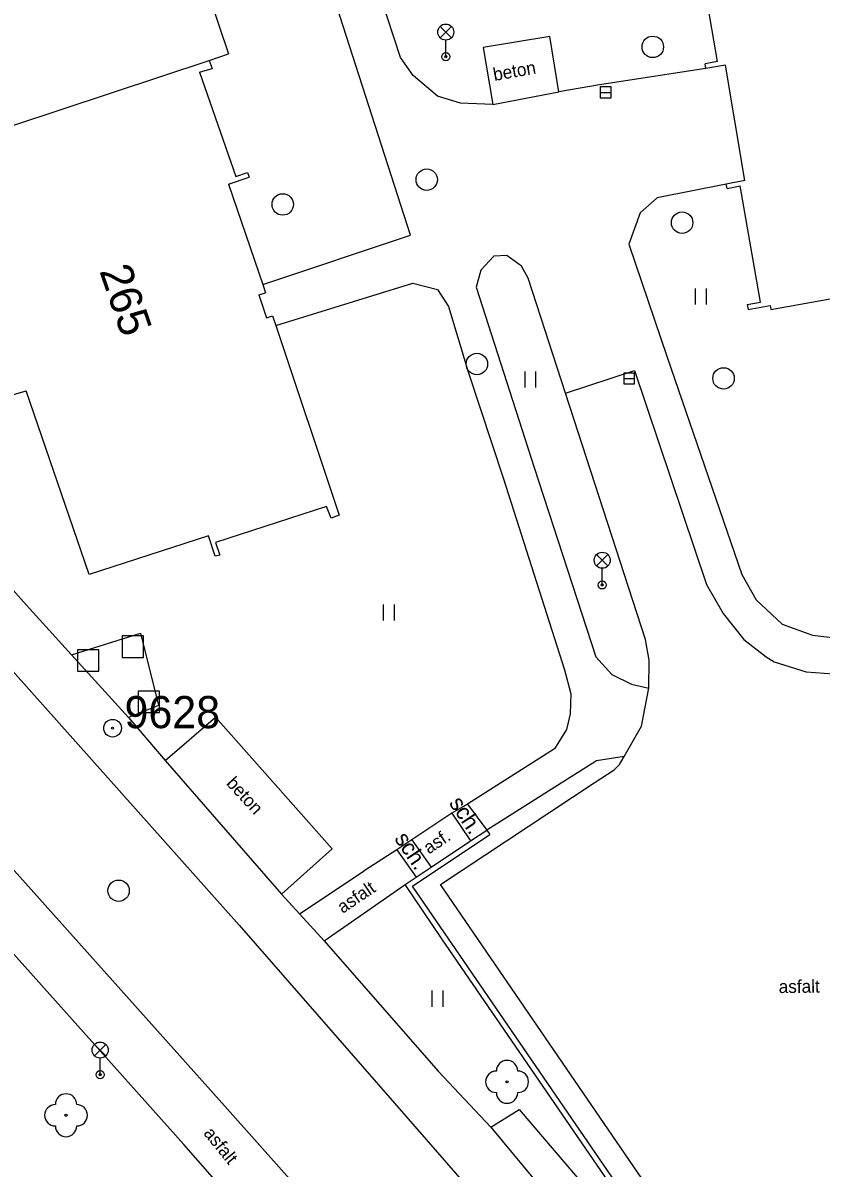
# Model space of a CAD drawing. Extents: x -492431 to -49218, y -1127123 to -112687.
# Drawn here: x -492324.3 to -492287, y -1126996.4 to -1126943 of the extents above; entities that cross this region are included whole.
import ezdxf

# ---------------------------------------------------------------- set-up
doc = ezdxf.new("R2010")
doc.units = 0
for name, color, linetype in [('Vrstva 10', 7, 'Continuous'), ('Vrstva 11', 7, 'Continuous'), ('Vrstva 22', 7, 'Continuous'), ('Vrstva 26', 7, 'Continuous'), ('Vrstva 27', 7, 'Continuous'), ('Vrstva 33', 7, 'Continuous'), ('Vrstva 36', 7, 'Continuous'), ('Vrstva 40', 7, 'Continuous'), ('Vrstva 42', 7, 'Continuous'), ('Vrstva 43', 7, 'Continuous'), ('Vrstva 5', 7, 'Continuous'), ('Vrstva 63', 7, 'Continuous')]:
    doc.layers.add(name, color=color, linetype=linetype)

msp = doc.modelspace()

# ---------------------------------------------------------------- linework, layer by layer
at = {"layer": 'Vrstva 10'}
for p, q in [((-492306.65, -1126944.57), (-492312.04, -1126928.07)), ((-492306.05, -1126945.42), (-492306.65, -1126944.57)), ((-492304.92, -1126946.38), (-492306.05, -1126945.42)), ((-492303.85, -1126946.71), (-492304.92, -1126946.38)), ((-492302.34, -1126946.76), (-492303.85, -1126946.71)), ((-492298.94, -1126960.23), (-492295.73, -1126959.17)), ((-492295.73, -1126959.17), (-492292.37, -1126969.15)), ((-492295.21, -1126971.71), (-492298.94, -1126960.23)), ((-492324.24, -1126969.96), (-492326.41, -1126967.51)), ((-492292.37, -1126969.15), (-492291.59, -1126970.51)), ((-492291.59, -1126970.51), (-492290.62, -1126971.71)), ((-492295.04, -1126972.68), (-492295.21, -1126971.71)), ((-492290.62, -1126971.71), (-492289.58, -1126972.52)), ((-492295.05, -1126973.99), (-492295.04, -1126972.68)), ((-492289.58, -1126972.52), (-492289.2, -1126972.75)), ((-492289.2, -1126972.75), (-492287.72, -1126973.22)), ((-492287.72, -1126973.22), (-492286.45, -1126973.32)), ((-492295.39, -1126975.75), (-492295.05, -1126973.99)), ((-492296.21, -1126977.17), (-492295.39, -1126975.75)), ((-492306.08, -1126983.22), (-492302.47, -1126980.81)), ((-492304.71, -1126985.68), (-492306.43, -1126983.14)), ((-492294.56, -1127000), (-492306.08, -1126983.22)), ((-492294.87, -1127000), (-492304.71, -1126985.68))]:
    msp.add_line(p, q, dxfattribs=at)
for points in [[(-492313.07, -1126955.16), (-492306.17, -1126952.86), (-492312.31, -1126933.84), (-492313.96, -1126934.43)], [(-492299.25, -1126946.17), (-492299.68, -1126943.6), (-492302.79, -1126944.11), (-492302.34, -1126946.76)], [(-492292.39, -1126945.09), (-492297.35, -1126945.85), (-492299.25, -1126946.17)], [(-492291.44, -1126950.48), (-492294.66, -1126951.12), (-492295.46, -1126951.82), (-492295.99, -1126953.28), (-492294.2, -1126958.55), (-492290.72, -1126968.68), (-492290.05, -1126969.86), (-492288.83, -1126971), (-492287.42, -1126971.52), (-492286.24, -1126971.66), (-492285.15, -1126971.46)], [(-492298.94, -1126960.23), (-492300.69, -1126954.87), (-492301, -1126954.31), (-492301.68, -1126953.81), (-492302.29, -1126953.84), (-492302.89, -1126954.49), (-492303.12, -1126955.29), (-492300.41, -1126963.69), (-492297.53, -1126972.53), (-492296.78, -1126973.35), (-492295.87, -1126973.8), (-492295.05, -1126973.99)], [(-492312.46, -1126957.08), (-492306.07, -1126955.1), (-492304.92, -1126955.4), (-492304.41, -1126956.18), (-492303.49, -1126959.24), (-492301.83, -1126964.22), (-492298.99, -1126973.13), (-492298.7, -1126974.25), (-492298.72, -1126975.18), (-492298.9, -1126975.91), (-492299.45, -1126976.82), (-492303.51, -1126979.39)], [(-492324.24, -1126969.96), (-492322, -1126972.43), (-492319.34, -1126975.35), (-492317.62, -1126977.35)], [(-492335.11, -1126970.78), (-492326.65, -1126980.29), (-492314.72, -1126993.62)], [(-492326.66, -1126971.05), (-492314.18, -1126985.03)], [(-492322, -1126972.43), (-492318.78, -1126971.42), (-492317.93, -1126974.79), (-492319.34, -1126975.35)], [(-492317.62, -1126977.35), (-492315.28, -1126975.33), (-492309.84, -1126981.47), (-492312.2, -1126983.59)], [(-492293.22, -1127000), (-492304.77, -1126983.14), (-492297.61, -1126978.4), (-492296.68, -1126977.79), (-492296.43, -1126977.55), (-492296.21, -1126977.17)], [(-492303.51, -1126979.39), (-492304.25, -1126979.82)], [(-492304.25, -1126979.82), (-492306.11, -1126981.06)], [(-492303.37, -1126981.11), (-492302.62, -1126980.61)], [(-492302.62, -1126980.61), (-492302.47, -1126980.81)], [(-492306.81, -1126981.53), (-492308.34, -1126982.51)], [(-492306.11, -1126981.06), (-492306.81, -1126981.53)], [(-492305.21, -1126982.33), (-492303.37, -1126981.11)], [(-492311.36, -1126984.5), (-492308.34, -1126982.51)], [(-492305.92, -1126982.8), (-492305.21, -1126982.33)], [(-492306.43, -1126983.14), (-492305.92, -1126982.8)], [(-492312.2, -1126983.59), (-492311.36, -1126984.5)], [(-492308.17, -1126984.35), (-492306.43, -1126983.14)], [(-492336.73, -1126985.35), (-492328.28, -1126983.94), (-492326.75, -1126984.43), (-492325.62, -1126985.37), (-492316.76, -1126995.26)], [(-492310.2, -1126985.76), (-492308.17, -1126984.35)], [(-492314.18, -1126985.03), (-492306.93, -1126993.34), (-492301.65, -1126999.39), (-492301.14, -1127000)], [(-492310.2, -1126985.76), (-492304.88, -1126991.85), (-492302.43, -1126994.46)], [(-492309.11, -1127000), (-492310.82, -1126998), (-492314.72, -1126993.62)], [(-492302.43, -1126994.46), (-492301.1, -1126993.63), (-492295.66, -1127000)], [(-492302.43, -1126994.46), (-492297.83, -1127000)], [(-492312.58, -1127000), (-492314.64, -1126997.68), (-492316.76, -1126995.26)]]:
    msp.add_lwpolyline(points, dxfattribs=at)
at = {"layer": 'Vrstva 11'}
msp.add_line((-492302.34, -1126946.76), (-492299.25, -1126946.17), dxfattribs=at)
for points in [[(-492296.21, -1126977.17), (-492297.49, -1126977.38), (-492302.62, -1126980.61)], [(-492317.62, -1126977.35), (-492312.2, -1126983.59)], [(-492303.51, -1126979.39), (-492302.62, -1126980.61)], [(-492304.25, -1126979.82), (-492303.37, -1126981.11)], [(-492306.81, -1126981.53), (-492305.92, -1126982.8)], [(-492306.11, -1126981.06), (-492305.21, -1126982.33)], [(-492311.36, -1126984.5), (-492310.2, -1126985.76)]]:
    msp.add_lwpolyline(points, dxfattribs=at)
at = {"layer": 'Vrstva 22'}
for centre in [(-492301.67, -1126992.34), (-492322.25, -1126993.9)]:
    msp.add_circle(centre, 0.05, dxfattribs=at)
for centre, start, end in [((-492301.67, -1126991.84), 360, 180), ((-492302.17, -1126992.34), 90, 270), ((-492301.17, -1126992.34), 270, 90), ((-492322.25, -1126993.4), 360, 180), ((-492301.67, -1126992.84), 180, 0), ((-492322.75, -1126993.9), 90, 270), ((-492321.75, -1126993.9), 270, 90), ((-492322.25, -1126994.4), 180, 0)]:
    msp.add_arc(centre, 0.5, start, end, dxfattribs=at)
at = {"layer": 'Vrstva 26'}
for points in [[(-492319.63, -1126972.55), (-492318.63, -1126972.55), (-492318.63, -1126971.55), (-492319.63, -1126971.55)], [(-492321.72, -1126973.19), (-492320.72, -1126973.19), (-492320.72, -1126972.19), (-492321.72, -1126972.19)], [(-492318.89, -1126975.12), (-492317.89, -1126975.12), (-492317.89, -1126974.12), (-492318.89, -1126974.12)]]:
    msp.add_lwpolyline(points, close=True, dxfattribs=at)
at = {"layer": 'Vrstva 27'}
for p, q in [((-492297.32, -1126946.2), (-492296.82, -1126946.2)), ((-492296.22, -1126959.55), (-492295.72, -1126959.55))]:
    msp.add_line(p, q, dxfattribs=at)
for points in [[(-492297.32, -1126946.45), (-492296.82, -1126946.45), (-492296.82, -1126945.95), (-492297.32, -1126945.95)], [(-492296.22, -1126959.8), (-492295.72, -1126959.8), (-492295.72, -1126959.3), (-492296.22, -1126959.3)]]:
    msp.add_lwpolyline(points, close=True, dxfattribs=at)
for centre in [(-492294.87, -1126944.08), (-492305.42, -1126950.27), (-492312.14, -1126951.43), (-492293.5, -1126952.28), (-492303.08, -1126958.87), (-492291.57, -1126959.54), (-492319.8, -1126983.43)]:
    msp.add_circle(centre, 0.5, dxfattribs=at)
at = {"layer": 'Vrstva 33'}
for p, q in [((-492304.795, -1126943.125), (-492304.265, -1126943.655)), ((-492304.795, -1126943.655), (-492304.265, -1126943.125)), ((-492304.53, -1126944.54), (-492304.53, -1126943.765)), ((-492297.495, -1126967.755), (-492296.965, -1126968.285)), ((-492297.495, -1126968.285), (-492296.965, -1126967.755)), ((-492297.23, -1126969.17), (-492297.23, -1126968.395)), ((-492320.925, -1126990.595), (-492320.395, -1126991.125)), ((-492320.925, -1126991.125), (-492320.395, -1126990.595)), ((-492320.66, -1126992.01), (-492320.66, -1126991.235))]:
    msp.add_line(p, q, dxfattribs=at)
for centre, radius in [((-492304.53, -1126943.39), 0.375), ((-492304.53, -1126944.54), 0.19), ((-492304.53, -1126944.54), 0.05), ((-492297.23, -1126968.02), 0.375), ((-492297.23, -1126969.17), 0.19), ((-492297.23, -1126969.17), 0.05), ((-492320.66, -1126990.86), 0.375), ((-492320.66, -1126992.01), 0.19), ((-492320.66, -1126992.01), 0.05)]:
    msp.add_circle(centre, radius, dxfattribs=at)
at = {"layer": 'Vrstva 36'}
for p, q in [((-492292.87, -1126956.09), (-492292.87, -1126955.34)), ((-492292.37, -1126956.09), (-492292.37, -1126955.34)), ((-492300.83, -1126959.97), (-492300.83, -1126959.22)), ((-492300.33, -1126959.97), (-492300.33, -1126959.22)), ((-492307.43, -1126970.83), (-492307.43, -1126970.08)), ((-492306.93, -1126970.83), (-492306.93, -1126970.08)), ((-492305.16, -1126988.84), (-492305.16, -1126988.09)), ((-492304.66, -1126988.84), (-492304.66, -1126988.09))]:
    msp.add_line(p, q, dxfattribs=at)
at = {"layer": 'Vrstva 5'}
for p, q in [((-492317.54, -1126935.81), (-492314.67, -1126944.41)), ((-492291.85, -1126944.76), (-492292.77, -1126939.35)), ((-492315.57, -1126944.71), (-492314.67, -1126944.41)), ((-492316.02, -1126945.26), (-492315.44, -1126945.09)), ((-492315.57, -1126944.71), (-492315.44, -1126945.09)), ((-492291.85, -1126944.76), (-492292.43, -1126944.87)), ((-492292.39, -1126945.09), (-492292.43, -1126944.87)), ((-492291.48, -1126944.93), (-492292.39, -1126945.09)), ((-492290.57, -1126950.31), (-492291.48, -1126944.93)), ((-492316.02, -1126945.26), (-492314.33, -1126950.12)), ((-492314.33, -1126950.12), (-492313.78, -1126949.94)), ((-492313.78, -1126949.94), (-492313.71, -1126950.16)), ((-492314.67, -1126950.48), (-492313.71, -1126950.16)), ((-492290.57, -1126950.31), (-492291.44, -1126950.48)), ((-492291.4, -1126950.68), (-492291.44, -1126950.48)), ((-492291.4, -1126950.68), (-492290.79, -1126950.56)), ((-492289.85, -1126955.98), (-492290.79, -1126950.56)), ((-492289.36, -1126956.32), (-492269.77, -1126952.84)), ((-492313.25, -1126955.65), (-492312.94, -1126955.55)), ((-492313.25, -1126955.65), (-492312.89, -1126956.71)), ((-492290.46, -1126956.1), (-492289.85, -1126955.98)), ((-492290.46, -1126956.1), (-492290.42, -1126956.32)), ((-492290.42, -1126956.32), (-492289.39, -1126956.14)), ((-492289.39, -1126956.14), (-492289.36, -1126956.32)), ((-492312.89, -1126956.71), (-492312.61, -1126956.62)), ((-492325.8, -1126960.61), (-492324.11, -1126960.12)), ((-492321.17, -1126968.68), (-492324.11, -1126960.12)), ((-492315.61, -1126966.88), (-492321.17, -1126968.68)), ((-492315.28, -1126967.19), (-492315.08, -1126967.78))]:
    msp.add_line(p, q, dxfattribs=at)
for points in [[(-492327, -1126948.5), (-492315.57, -1126944.71)], [(-492314.67, -1126950.48), (-492313.07, -1126955.16), (-492312.94, -1126955.55)], [(-492312.61, -1126956.62), (-492312.46, -1126957.08), (-492309.51, -1126965.92)], [(-492309.51, -1126965.92), (-492309.88, -1126966.05), (-492310.09, -1126965.51), (-492315.28, -1126967.19)], [(-492315.08, -1126967.78), (-492315.29, -1126967.83), (-492315.61, -1126966.88)]]:
    msp.add_lwpolyline(points, dxfattribs=at)
at = {"layer": 'Vrstva 63'}
for radius in [0.412, 0.05]:
    msp.add_circle((-492320.08, -1126975.85), radius, dxfattribs=at)

# ---------------------------------------------------------------- texts
at = {"layer": 'Vrstva 40'}
for s, rotation, p in [('beton', 10.1444, (-492302.265, -1126945.672)), ('beton', 312.7588, (-492314.809, -1126978.45)), ('asf.', 33.9377, (-492305.317, -1126981.746)), ('asfalt', 33.9377, (-492309.343, -1126984.512)), ('asfalt', 0.6341, (-492288.993, -1126988.203)), ('asfalt', 309.0335, (-492315.863, -1126994.752))]:
    msp.add_text(s, height=0.6, rotation=rotation, dxfattribs=at).set_placement(p)
at = {"layer": 'Vrstva 42'}
for p in [(-492304.403, -1126979.345), (-492306.953, -1126981.005)]:
    msp.add_text('sch.', height=0.75, rotation=303.7879, dxfattribs=at).set_placement(p)
at = {"layer": 'Vrstva 43'}
msp.add_text('265', height=1.5, rotation=288.8655, dxfattribs=at).set_placement((-492320.705, -1126954.522))
at = {"layer": 'Vrstva 63'}
msp.add_text(' 9628', height=1.5, dxfattribs=at).set_placement((-492320.08, -1126975.85))

doc.saveas('drawing.dxf')
